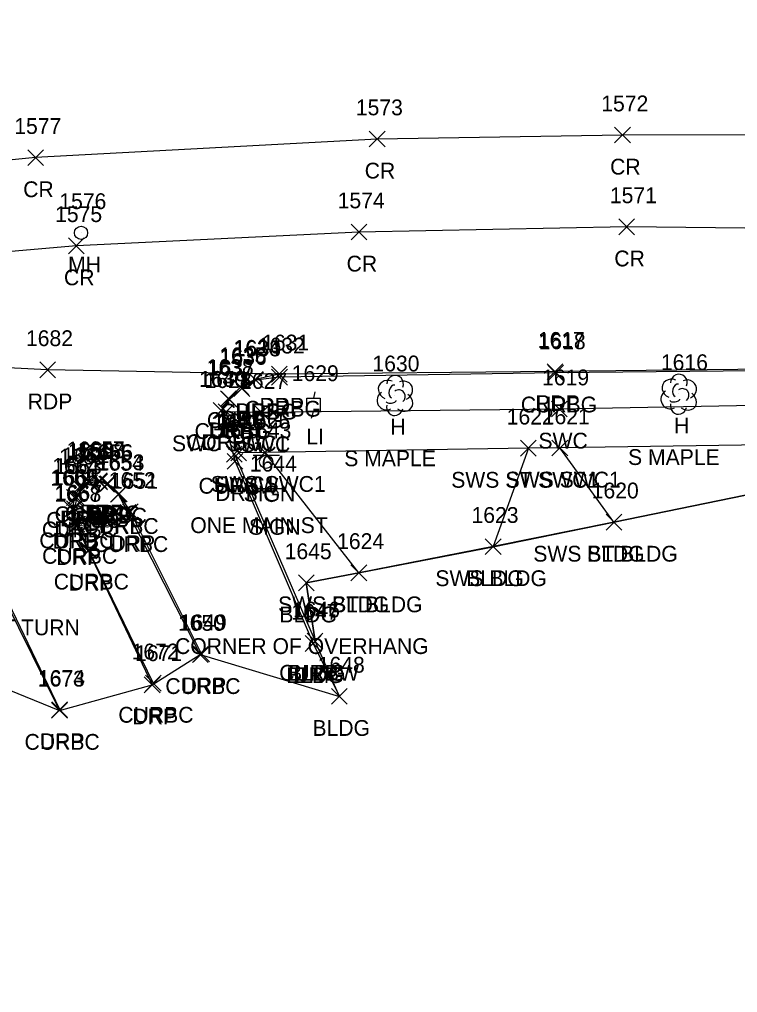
# Model space of a CAD drawing. Extents: x 1715662 to 1717487, y 887396 to 890004.
# Drawn here: x 1716283.7 to 1716374.6, y 888134.9 to 888258 of the extents above; entities that cross this region are included whole.
import ezdxf

# ---------------------------------------------------------------- set-up
doc = ezdxf.new("R2010")
doc.units = 0
for name, color, linetype in [('L_A', 7, 'Continuous'), ('L_C', 7, 'Continuous'), ('L_I', 7, 'Continuous'), ('L_TIC', 7, 'Continuous'), ('LBC', 7, 'Continuous'), ('LSOGP', 7, 'Continuous'), ('LTD', 7, 'Continuous'), ('P_A', 7, 'Continuous'), ('P_I', 7, 'Continuous'), ('P_TIC', 7, 'Continuous'), ('PET', 7, 'Continuous'), ('PRC', 7, 'Continuous'), ('R_A', 7, 'Continuous'), ('R_I', 7, 'Continuous'), ('R_TIC', 7, 'Continuous'), ('RC', 7, 'Continuous'), ('RDP', 7, 'Continuous'), ('RSW', 7, 'Continuous'), ('S_A', 7, 'Continuous'), ('S_C', 7, 'Continuous'), ('S_I', 7, 'Continuous'), ('SSGN', 7, 'Continuous'), ('U_A', 7, 'Continuous'), ('U_I', 7, 'Continuous'), ('ULP', 7, 'Continuous'), ('UUMH', 7, 'Continuous')]:
    doc.layers.add(name, color=color, linetype=linetype)

msp = doc.modelspace()

# ---------------------------------------------------------------- linework, layer by layer
at = {"layer": 'L_TIC'}
for points in [[(1716357.99, 888193.4), (1716359.99, 888195.4)], [(1716359.99, 888193.4), (1716357.99, 888195.4)], [(1716342.7, 888190.3), (1716344.7, 888192.3)], [(1716344.7, 888190.3), (1716342.7, 888192.3)], [(1716325.69, 888186.99), (1716327.69, 888188.99)], [(1716327.69, 888186.99), (1716325.69, 888188.99)], [(1716319.05, 888185.71), (1716321.05, 888187.71)], [(1716321.05, 888185.71), (1716319.05, 888187.71)], [(1716319.91, 888178.04), (1716321.91, 888180.04)], [(1716321.91, 888178.04), (1716319.91, 888180.04)], [(1716320.15, 888178.33), (1716322.15, 888180.33)], [(1716322.15, 888178.33), (1716320.15, 888180.33)], [(1716323.24, 888171.35), (1716325.24, 888173.35)], [(1716325.24, 888171.35), (1716323.24, 888173.35)]]:
    msp.add_lwpolyline(points, dxfattribs=at)
at = {"layer": 'LBC'}
msp.add_lwpolyline([(1716429.38, 888098.53), (1716421.79, 888136.33), (1716414.93, 888170.83), (1716409.81, 888196.87), (1716408.19, 888204.6), (1716403.96, 888203.43), (1716387.16, 888200.16), (1716358.99, 888194.4), (1716343.7, 888191.3), (1716326.69, 888187.99), (1716320.05, 888186.71), (1716321.15, 888179.33), (1716320.91, 888179.04), (1716324.24, 888172.35)], dxfattribs=at)
at = {"layer": 'LSOGP'}
msp.add_lwpolyline([(1716277.08, 888175.31), (1716288.81, 888170.58), (1716300.55, 888173.81), (1716306.63, 888177.65), (1716324.24, 888172.35), (1716321.15, 888179.33), (1716320.05, 888186.71), (1716326.69, 888187.99), (1716343.7, 888191.29), (1716358.99, 888194.39), (1716387.16, 888200.16), (1716403.96, 888203.43), (1716408.19, 888204.59), (1716409.81, 888196.87), (1716414.93, 888170.83), (1716421.79, 888136.33), (1716429.38, 888098.52)], dxfattribs=at)
at = {"layer": 'LTD'}
for p, q in [((1716331.25, 888210.47), (1716331.25, 888210.47)), ((1716331.25, 888210.47), (1716331.25, 888210.47)), ((1716367.16, 888210.63), (1716367.16, 888210.63)), ((1716367.16, 888210.63), (1716367.16, 888210.63))]:
    msp.add_line(p, q, dxfattribs=at)
for centre in [(1716331.29, 888211.91), (1716367.21, 888212.06)]:
    msp.add_arc(centre, 1.05, 335.5272, 180.9563, dxfattribs=at)
for centre, major_axis, ratio, start_param, end_param in [((1716330.45, 888211.14), (1.21, -0.51), 0.895232, 1.570796, 4.712389), ((1716332.29, 888211.06), (-1.14, -0.48), 0.949671, 1.570796, 4.712389), ((1716366.37, 888211.29), (1.21, -0.51), 0.895232, 1.570796, 4.712389), ((1716368.2, 888211.21), (-1.14, -0.48), 0.949671, 1.570796, 4.712389), ((1716330.16, 888209.77), (0.58, -1.04), 0.959034, 3.141593, 6.283185), ((1716331.04, 888210.93), (-0.208, -0.792), 0.645439, 3.141593, 6.283185), ((1716331.75, 888210.31), (-0.5, 0.667), 0.989748, 3.141593, 6.283185), ((1716366.08, 888209.92), (0.58, -1.04), 0.959034, 3.141593, 6.283185), ((1716366.95, 888211.08), (-0.208, -0.792), 0.645439, 3.141593, 6.283185), ((1716367.66, 888210.46), (-0.5, 0.667), 0.989748, 3.141593, 6.283185), ((1716330.79, 888209.72), (-0.625, -0.083), 0.423636, 0, 3.141593), ((1716332.25, 888209.64), (-1.09, 0.79), 0.841452, 1.570796, 4.712389), ((1716366.7, 888209.88), (-0.625, -0.083), 0.423636, 0, 3.141593), ((1716368.16, 888209.79), (-1.09, 0.79), 0.841452, 1.570796, 4.712389), ((1716331.25, 888208.97), (0.26, 1.06), 0.942809, 1.570796, 4.712389), ((1716367.16, 888209.13), (0.26, 1.06), 0.942809, 1.570796, 4.712389)]:
    msp.add_ellipse(centre, major_axis=major_axis, ratio=ratio, start_param=start_param, end_param=end_param, dxfattribs=at)
at = {"layer": 'P_TIC'}
for points in [[(1716359.07, 888242.38), (1716361.07, 888244.38)], [(1716361.07, 888242.38), (1716359.07, 888244.38)], [(1716328.01, 888241.88), (1716330.01, 888243.88)], [(1716330.01, 888241.88), (1716328.01, 888243.88)], [(1716284.79, 888239.52), (1716286.79, 888241.52)], [(1716286.79, 888239.52), (1716284.79, 888241.52)], [(1716325.71, 888230.11), (1716327.71, 888232.11)], [(1716327.71, 888230.11), (1716325.71, 888232.11)], [(1716359.6, 888230.76), (1716361.6, 888232.76)], [(1716361.6, 888230.76), (1716359.6, 888232.76)], [(1716289.95, 888228.37), (1716291.95, 888230.37)], [(1716291.95, 888228.37), (1716289.95, 888230.37)], [(1716286.31, 888212.67), (1716288.31, 888214.67)], [(1716288.31, 888212.67), (1716286.31, 888214.67)], [(1716315.63, 888212.12), (1716317.63, 888214.12)], [(1716317.63, 888212.12), (1716315.63, 888214.12)], [(1716350.52, 888212.45), (1716352.52, 888214.45)], [(1716352.52, 888212.45), (1716350.52, 888214.45)]]:
    msp.add_lwpolyline(points, dxfattribs=at)
at = {"layer": 'PET'}
msp.add_lwpolyline([(1716420.85, 888214.16), (1716393.96, 888213.91), (1716351.52, 888213.45), (1716316.63, 888213.12), (1716287.31, 888213.67), (1716263.82, 888214.85), (1716262.16, 888214.92), (1716260.17, 888214.76), (1716250.4, 888213.03), (1716244.38, 888211.92), (1716239.31, 888205.59), (1716232.02, 888203.34), (1716223.89, 888200.87), (1716211.25, 888196.69), (1716194.26, 888190.63), (1716179.32, 888184.63), (1716135.65, 888166.65), (1716133.73, 888165.8), (1716132.45, 888164.77), (1716131.74, 888163.68), (1716109.75, 888154.13), (1716108.2, 888154.22), (1716106.26, 888154.03), (1716102, 888152.34)], dxfattribs=at)
at = {"layer": 'PRC'}
for points in [[(1716612.85, 888359.68), (1716612.17, 888345.49), (1716610.23, 888325.05), (1716599.91, 888295.77), (1716584.78, 888274.26), (1716560.31, 888253.42), (1716535.28, 888241.32), (1716471.98, 888238.42), (1716446.91, 888240.45), (1716423.44, 888242.23), (1716395.99, 888243.46), (1716360.07, 888243.38), (1716329.01, 888242.88), (1716285.79, 888240.52), (1716253.17, 888237.3), (1716220.47, 888232.04), (1716184.13, 888222.3), (1716155.75, 888211.83), (1716125.79, 888199.82), (1716096.66, 888186.57)], [(1716552.72, 888226.16), (1716521.3, 888223.53), (1716490.76, 888225.55), (1716471.3, 888227.05), (1716451.95, 888228.65), (1716428.34, 888230.29), (1716394.24, 888231.4), (1716360.6, 888231.76), (1716326.71, 888231.11), (1716290.95, 888229.37), (1716251.51, 888225.94), (1716222.8, 888221), (1716188.27, 888210.85), (1716159.49, 888199.86), (1716131.41, 888188.25), (1716103, 888175.83)]]:
    msp.add_lwpolyline(points, dxfattribs=at)
at = {"layer": 'R_TIC'}
for points in [[(1716312.57, 888211.45), (1716314.57, 888213.45)], [(1716314.57, 888211.45), (1716312.57, 888213.45)], [(1716312.63, 888211.38), (1716314.63, 888213.38)], [(1716314.63, 888211.38), (1716312.63, 888213.38)], [(1716315.63, 888212.12), (1716317.63, 888214.12)], [(1716317.63, 888212.12), (1716315.63, 888214.12)], [(1716315.65, 888211.74), (1716317.65, 888213.74)], [(1716317.65, 888211.74), (1716315.65, 888213.74)], [(1716350.62, 888212.28), (1716352.62, 888214.28)], [(1716352.62, 888212.28), (1716350.62, 888214.28)], [(1716310.77, 888210.5), (1716312.77, 888212.5)], [(1716312.77, 888210.5), (1716310.77, 888212.5)], [(1716310.89, 888210.31), (1716312.89, 888212.31)], [(1716312.89, 888210.31), (1716310.89, 888212.31)], [(1716309.19, 888209.01), (1716311.19, 888211.01)], [(1716311.19, 888209.01), (1716309.19, 888211.01)], [(1716309.33, 888208.92), (1716311.33, 888210.92)], [(1716311.33, 888208.92), (1716309.33, 888210.92)], [(1716351.07, 888207.71), (1716353.07, 888209.71)], [(1716353.07, 888207.71), (1716351.07, 888209.71)], [(1716308.28, 888207.52), (1716310.28, 888209.52)], [(1716310.28, 888207.52), (1716308.28, 888209.52)], [(1716308.29, 888207.51), (1716310.29, 888209.51)], [(1716310.29, 888207.51), (1716308.29, 888209.51)], [(1716308.91, 888207.37), (1716310.91, 888209.37)], [(1716310.91, 888207.37), (1716308.91, 888209.37)], [(1716308.91, 888207.37), (1716310.91, 888209.37)], [(1716310.91, 888207.37), (1716308.91, 888209.37)], [(1716313.41, 888207.26), (1716315.41, 888209.26)], [(1716315.41, 888207.26), (1716313.41, 888209.26)], [(1716347.16, 888202.75), (1716349.16, 888204.75)], [(1716349.16, 888202.75), (1716347.16, 888204.75)], [(1716347.16, 888202.75), (1716349.16, 888204.75)], [(1716349.16, 888202.75), (1716347.16, 888204.75)], [(1716351.14, 888202.78), (1716353.14, 888204.78)], [(1716353.14, 888202.78), (1716351.14, 888204.78)], [(1716351.14, 888202.78), (1716353.14, 888204.78)], [(1716353.14, 888202.78), (1716351.14, 888204.78)], [(1716309.95, 888202), (1716311.95, 888204)], [(1716311.95, 888202), (1716309.95, 888204)], [(1716310.49, 888202.17), (1716312.49, 888204.17)], [(1716312.49, 888202.17), (1716310.49, 888204.17)], [(1716313.81, 888202.23), (1716315.81, 888204.23)], [(1716315.81, 888202.23), (1716313.81, 888204.23)], [(1716313.81, 888202.23), (1716315.81, 888204.23)], [(1716315.81, 888202.23), (1716313.81, 888204.23)], [(1716310.03, 888201.08), (1716312.03, 888203.08)], [(1716312.03, 888201.08), (1716310.03, 888203.08)], [(1716290.39, 888197.86), (1716292.39, 888199.86)], [(1716292.39, 888197.86), (1716290.39, 888199.86)], [(1716291.6, 888198.59), (1716293.6, 888200.59)], [(1716293.6, 888198.59), (1716291.6, 888200.59)], [(1716291.61, 888198.39), (1716293.61, 888200.39)], [(1716293.61, 888198.39), (1716291.61, 888200.39)], [(1716292.86, 888198.62), (1716294.86, 888200.62)], [(1716294.86, 888198.62), (1716292.86, 888200.62)], [(1716292.89, 888198.49), (1716294.89, 888200.49)], [(1716294.89, 888198.49), (1716292.89, 888200.49)], [(1716293.78, 888198.2), (1716295.78, 888200.2)], [(1716295.78, 888198.2), (1716293.78, 888200.2)], [(1716293.96, 888198.26), (1716295.96, 888200.26)], [(1716295.96, 888198.26), (1716293.96, 888200.26)], [(1716289.68, 888196.51), (1716291.68, 888198.51)], [(1716291.68, 888196.51), (1716289.68, 888198.51)], [(1716290.55, 888197.68), (1716292.55, 888199.68)], [(1716292.55, 888197.68), (1716290.55, 888199.68)], [(1716295.27, 888196.91), (1716297.27, 888198.91)], [(1716297.27, 888196.91), (1716295.27, 888198.91)], [(1716295.36, 888196.97), (1716297.36, 888198.97)], [(1716297.36, 888196.97), (1716295.36, 888198.97)], [(1716290, 888196.47), (1716292, 888198.47)], [(1716292, 888196.47), (1716290, 888198.47)], [(1716289.44, 888195.02), (1716291.44, 888197.02)], [(1716291.44, 888195.02), (1716289.44, 888197.02)], [(1716289.68, 888195.09), (1716291.68, 888197.09)], [(1716291.68, 888195.09), (1716289.68, 888197.09)], [(1716296.49, 888194.62), (1716298.49, 888196.62)], [(1716298.49, 888194.62), (1716296.49, 888196.62)], [(1716296.78, 888194.72), (1716298.78, 888196.72)], [(1716298.78, 888194.72), (1716296.78, 888196.72)], [(1716289.94, 888192.98), (1716291.94, 888194.98)], [(1716291.94, 888192.98), (1716289.94, 888194.98)], [(1716290.03, 888193.13), (1716292.03, 888195.13)], [(1716292.03, 888193.13), (1716290.03, 888195.13)], [(1716357.99, 888193.4), (1716359.99, 888195.4)], [(1716359.99, 888193.4), (1716357.99, 888195.4)], [(1716291.48, 888189.74), (1716293.48, 888191.74)], [(1716293.48, 888189.74), (1716291.48, 888191.74)], [(1716291.5, 888189.87), (1716293.5, 888191.87)], [(1716293.5, 888189.87), (1716291.5, 888191.87)], [(1716342.7, 888190.3), (1716344.7, 888192.3)], [(1716344.7, 888190.3), (1716342.7, 888192.3)], [(1716325.69, 888186.99), (1716327.69, 888188.99)], [(1716327.69, 888186.99), (1716325.69, 888188.99)], [(1716319.91, 888178.04), (1716321.91, 888180.04)], [(1716321.91, 888178.04), (1716319.91, 888180.04)], [(1716320.15, 888178.33), (1716322.15, 888180.33)], [(1716322.15, 888178.33), (1716320.15, 888180.33)], [(1716305.63, 888176.65), (1716307.63, 888178.65)], [(1716307.63, 888176.65), (1716305.63, 888178.65)], [(1716305.78, 888176.72), (1716307.78, 888178.72)], [(1716307.78, 888176.72), (1716305.78, 888178.72)], [(1716299.55, 888172.81), (1716301.55, 888174.81)], [(1716301.55, 888172.81), (1716299.55, 888174.81)], [(1716299.68, 888173.02), (1716301.68, 888175.02)], [(1716301.68, 888173.02), (1716299.68, 888175.02)], [(1716287.81, 888169.59), (1716289.81, 888171.59)], [(1716289.81, 888169.59), (1716287.81, 888171.59)], [(1716287.84, 888169.67), (1716289.84, 888171.67)], [(1716289.84, 888169.67), (1716287.84, 888171.67)]]:
    msp.add_lwpolyline(points, dxfattribs=at)
at = {"layer": 'RC'}
for points in [[(1716420.86, 888213.84), (1716394, 888213.71), (1716351.62, 888213.28), (1716316.65, 888212.74), (1716313.63, 888212.38), (1716311.89, 888211.31), (1716310.33, 888209.92), (1716309.29, 888208.51)], [(1716310.95, 888203), (1716321.15, 888179.33)], [(1716288.81, 888170.59), (1716273.34, 888201.87)], [(1716306.63, 888177.65), (1716297.49, 888195.62), (1716296.27, 888197.91), (1716294.78, 888199.2), (1716293.89, 888199.49), (1716292.61, 888199.39), (1716291.55, 888198.68), (1716291, 888197.47), (1716290.68, 888196.09), (1716291.03, 888194.13), (1716292.5, 888190.87), (1716300.68, 888174.02)]]:
    msp.add_lwpolyline(points, dxfattribs=at)
at = {"layer": 'RDP'}
for points in [[(1716288.84, 888170.67), (1716273.82, 888201.89), (1716270.81, 888208.33), (1716268.77, 888212.63), (1716266.75, 888213.93), (1716265.39, 888214.45), (1716263.82, 888214.85)], [(1716316.63, 888213.12), (1716313.57, 888212.45), (1716311.77, 888211.5), (1716310.19, 888210.01), (1716309.28, 888208.52), (1716311.03, 888202.08), (1716320.91, 888179.04)], [(1716306.78, 888177.72), (1716297.78, 888195.72), (1716296.36, 888197.97), (1716294.96, 888199.26), (1716293.86, 888199.62), (1716292.6, 888199.59), (1716291.39, 888198.86), (1716290.68, 888197.51), (1716290.44, 888196.02), (1716290.94, 888193.98), (1716292.48, 888190.74), (1716300.55, 888173.81)]]:
    msp.add_lwpolyline(points, dxfattribs=at)
at = {"layer": 'RSW'}
for points in [[(1716425.59, 888209.88), (1716390.21, 888209.42), (1716352.07, 888208.71), (1716314.41, 888208.26), (1716309.91, 888208.37)], [(1716426.58, 888205.04), (1716408.19, 888204.6), (1716404.22, 888204.46), (1716383.73, 888204.28), (1716352.14, 888203.78), (1716348.16, 888203.75), (1716314.81, 888203.23), (1716311.49, 888203.17), (1716309.91, 888208.37)], [(1716348.16, 888203.75), (1716343.7, 888191.3)], [(1716358.99, 888194.4), (1716352.14, 888203.78)], [(1716326.69, 888187.99), (1716314.81, 888203.23)]]:
    msp.add_lwpolyline(points, dxfattribs=at)
at = {"layer": 'SSGN'}
for p, q in [((1716313.33, 888202.87), (1716316.66, 888202.87)), ((1716314.97, 888202.03), (1716314.97, 888202.03)), ((1716314.01, 888198.66), (1716317.34, 888198.66)), ((1716315.66, 888197.82), (1716315.66, 888197.82))]:
    msp.add_line(p, q, dxfattribs=at)
for centre in [(1716314.97, 888202.03), (1716315.66, 888197.82)]:
    msp.add_circle(centre, 0.833, dxfattribs=at)
at = {"layer": 'ULP'}
for p, q in [((1716321.12, 888210.9), (1716320.96, 888210.07)), ((1716320.12, 888208.4), (1716320.12, 888210.07)), ((1716320.12, 888210.07), (1716321.79, 888210.07)), ((1716321.79, 888210.07), (1716321.79, 888208.4)), ((1716321.79, 888208.4), (1716320.12, 888208.4)), ((1716320.71, 888207.57), (1716320.96, 888208.4)), ((1716320.96, 888209.24), (1716320.96, 888209.24))]:
    msp.add_line(p, q, dxfattribs=at)
at = {"layer": 'UUMH'}
for p, q in [((1716291.54, 888231.01), (1716291.54, 888231.01)), ((1716292.37, 888231.01), (1716292.37, 888231.01))]:
    msp.add_line(p, q, dxfattribs=at)
msp.add_circle((1716291.54, 888231.01), 0.833, dxfattribs=at)

# ---------------------------------------------------------------- texts
at = {"layer": 'L_A'}
for s, p in [('H', (1716330.68, 888205.47)), ('H', (1716366.59, 888205.63)), ('BLDG', (1716355.58, 888189.4)), ('BLDG', (1716340.29, 888186.3)), ('BLDG', (1716323.28, 888182.99)), ('BLDG', (1716316.64, 888181.71)), ('BLDG', (1716317.75, 888174.33)), ('BLDG', (1716317.5, 888174.04)), ('BLDG', (1716320.83, 888167.35))]:
    msp.add_text(s, height=2, dxfattribs=at).set_placement(p)
at = {"layer": 'L_C'}
for s, p in [('S MAPLE', (1716324.85, 888201.47)), ('S MAPLE', (1716360.77, 888201.63)), ('CORNER OF OVERHANG', (1716303.44, 888177.71))]:
    msp.add_text(s, height=2, dxfattribs=at).set_placement(p)
at = {"layer": 'L_I'}
for s, p in [('1630', (1716328.42, 888213.47)), ('1616', (1716364.93, 888213.63)), ('1620', (1716356.17, 888197.4)), ('1623', (1716340.96, 888194.3)), ('1624', (1716323.95, 888190.99)), ('1645', (1716317.31, 888189.71)), ('1647', (1716318.17, 888182.04)), ('1646', (1716318.36, 888182.33)), ('1648', (1716321.5, 888175.35))]:
    msp.add_text(s, height=2, dxfattribs=at).set_placement(p)
at = {"layer": 'P_A'}
for s, p in [('CR', (1716358.5, 888238.38)), ('CR', (1716327.44, 888237.88)), ('CR', (1716284.22, 888235.52)), ('CR', (1716325.15, 888226.11)), ('CR', (1716359.03, 888226.76)), ('CR', (1716289.38, 888224.37)), ('RDP', (1716284.79, 888208.67)), ('RDP', (1716314.12, 888208.12)), ('RDP', (1716349.01, 888208.45))]:
    msp.add_text(s, height=2, dxfattribs=at).set_placement(p)
at = {"layer": 'P_I'}
for s, p in [('1573', (1716326.32, 888245.88)), ('1572', (1716357.38, 888246.38)), ('1577', (1716283.09, 888243.52)), ('1571', (1716358.47, 888234.76)), ('1574', (1716324.02, 888234.11)), ('1575', (1716288.26, 888232.37)), ('1682', (1716284.57, 888216.67)), ('1617', (1716349.35, 888216.45)), ('1631', (1716314.46, 888216.12))]:
    msp.add_text(s, height=2, dxfattribs=at).set_placement(p)
at = {"layer": 'R_A'}
for s, p in [('CURBG', (1716312.24, 888207.74)), ('DRP', (1716314.12, 888208.12)), ('CURBG', (1716347.2, 888208.28)), ('CURBG', (1716307.47, 888206.31)), ('CURBG', (1716309.21, 888207.38)), ('DRP', (1716309.26, 888206.5)), ('DRP', (1716311.06, 888207.45)), ('CURBG', (1716305.91, 888204.92)), ('DRP', (1716307.67, 888205.01)), ('SWC SWC1', (1716303.05, 888203.37)), ('SWC SWC1', (1716303.05, 888203.37)), ('CURBG', (1716304.87, 888203.51)), ('DRP', (1716306.77, 888203.52)), ('SWC', (1716311.78, 888203.26)), ('SWC', (1716349.43, 888203.71)), ('CURBW', (1716306.41, 888198)), ('SWS SWC1', (1716307.94, 888198.23)), ('SWS SWC1', (1716307.94, 888198.23)), ('SWC1', (1716308.53, 888198.17)), ('SWS ST SWC1', (1716338.39, 888198.75)), ('SWS ST SWC1', (1716338.39, 888198.75)), ('SWS SWC1', (1716345.28, 888198.78)), ('SWS SWC1', (1716345.28, 888198.78)), ('DRP', (1716308.52, 888197.08)), ('CURBC', (1716288.2, 888194.39)), ('CURBC', (1716289.48, 888194.49)), ('DRP', (1716290.09, 888194.59)), ('CURBC', (1716290.36, 888194.2)), ('DRP', (1716291.34, 888194.62)), ('DRP', (1716292.45, 888194.26)), ('CURBC', (1716287.13, 888193.68)), ('DRP', (1716288.88, 888193.86)), ('CURBC', (1716291.85, 888192.91)), ('DRP', (1716293.84, 888192.97)), ('CURBC', (1716286.59, 888192.47)), ('DRP', (1716288.17, 888192.51)), ('CURBC', (1716286.26, 888191.09)), ('DRP', (1716287.93, 888191.02)), ('CURBC', (1716293.07, 888190.62)), ('DRP', (1716295.27, 888190.72)), ('CURBC', (1716286.61, 888189.13)), ('SWS ST BLDG', (1716348.78, 888189.4)), ('DRP', (1716288.42, 888188.98)), ('CURBC', (1716288.09, 888185.87)), ('DRP', (1716289.96, 888185.74)), ('SWS BLDG', (1716336.38, 888186.3)), ('SWS ST BLDG', (1716316.48, 888182.99)), ('CURBW', (1716316.62, 888174.33)), ('DRP', (1716318.4, 888174.04)), ('CURBC', (1716302.21, 888172.65)), ('DRP', (1716304.27, 888172.72)), ('CURBC', (1716296.26, 888169.02)), ('DRP', (1716298.04, 888168.81)), ('CURBC', (1716284.39, 888165.59)), ('DRP', (1716286.33, 888165.67))]:
    msp.add_text(s, height=2, dxfattribs=at).set_placement(p)
at = {"layer": 'R_I'}
for s, p in [('1618', (1716349.45, 888216.28)), ('1634', (1716310.83, 888215.45)), ('1633', (1716310.89, 888215.38)), ('1632', (1716313.91, 888215.74)), ('1631', (1716314.46, 888216.12)), ('1635', (1716309.03, 888214.5)), ('1636', (1716309.09, 888214.31)), ('1638', (1716307.44, 888213.01)), ('1637', (1716307.59, 888212.92)), ('1640', (1716306.46, 888211.51)), ('1639', (1716306.53, 888211.52)), ('1628', (1716307.17, 888211.37)), ('1628', (1716307.17, 888211.37)), ('1627', (1716311.67, 888211.26)), ('1619', (1716349.89, 888211.71)), ('1622', (1716345.41, 888206.75)), ('1622', (1716345.41, 888206.75)), ('1621', (1716349.97, 888206.78)), ('1621', (1716349.97, 888206.78)), ('1642', (1716308.21, 888206)), ('1626', (1716308.7, 888206.17)), ('1641', (1716308.85, 888205.08)), ('1625', (1716312.07, 888206.23)), ('1625', (1716312.07, 888206.23)), ('1657', (1716291.12, 888202.62)), ('1662', (1716288.76, 888201.68)), ('1661', (1716289.17, 888201.86)), ('1660', (1716289.73, 888202.59)), ('1659', (1716289.87, 888202.39)), ('1658', (1716291.15, 888202.49)), ('1655', (1716292.04, 888202.2)), ('1656', (1716292.17, 888202.26)), ('1664', (1716287.89, 888200.51)), ('1663', (1716288.22, 888200.47)), ('1654', (1716293.53, 888200.91)), ('1653', (1716293.62, 888200.97)), ('1665', (1716287.65, 888199.02)), ('1666', (1716287.84, 888199.09)), ('1652', (1716295.04, 888198.72)), ('1651', (1716295.32, 888198.62)), ('1668', (1716288.15, 888196.98)), ('1667', (1716288.24, 888197.13)), ('1620', (1716356.17, 888197.4)), ('1623', (1716340.96, 888194.3)), ('1670', (1716289.68, 888193.87)), ('1669', (1716289.68, 888193.74)), ('1624', (1716323.95, 888190.99)), ('1647', (1716318.17, 888182.04)), ('1646', (1716318.36, 888182.33)), ('1650', (1716303.8, 888180.65)), ('1649', (1716304.03, 888180.72)), ('1672', (1716297.94, 888177.02)), ('1671', (1716298.38, 888176.81)), ('1673', (1716286.07, 888173.59)), ('1674', (1716286.1, 888173.67))]:
    msp.add_text(s, height=2, dxfattribs=at).set_placement(p)
at = {"layer": 'S_A'}
for p in [(1716312.11, 888197.01), (1716312.79, 888192.8)]:
    msp.add_text('SIGN', height=2, dxfattribs=at).set_placement(p)
at = {"layer": 'S_C'}
for s, p in [('ONE MAIN ST', (1716305.37, 888193.01)), ('DO NOT ENTER/ NO LEFT TURN', (1716250.22, 888180.08))]:
    msp.add_text(s, height=2, dxfattribs=at).set_placement(p)
at = {"layer": 'S_I'}
for s, p in [('1643', (1716312.21, 888205.01)), ('1644', (1716312.9, 888200.8))]:
    msp.add_text(s, height=2, dxfattribs=at).set_placement(p)
at = {"layer": 'U_A'}
for s, p in [('MH', (1716289.9, 888226.01)), ('LI', (1716320.06, 888204.24))]:
    msp.add_text(s, height=2, dxfattribs=at).set_placement(p)
at = {"layer": 'U_I'}
for s, p in [('1576', (1716288.79, 888234.01)), ('1629', (1716318.21, 888212.24))]:
    msp.add_text(s, height=2, dxfattribs=at).set_placement(p)

doc.saveas('drawing.dxf')
